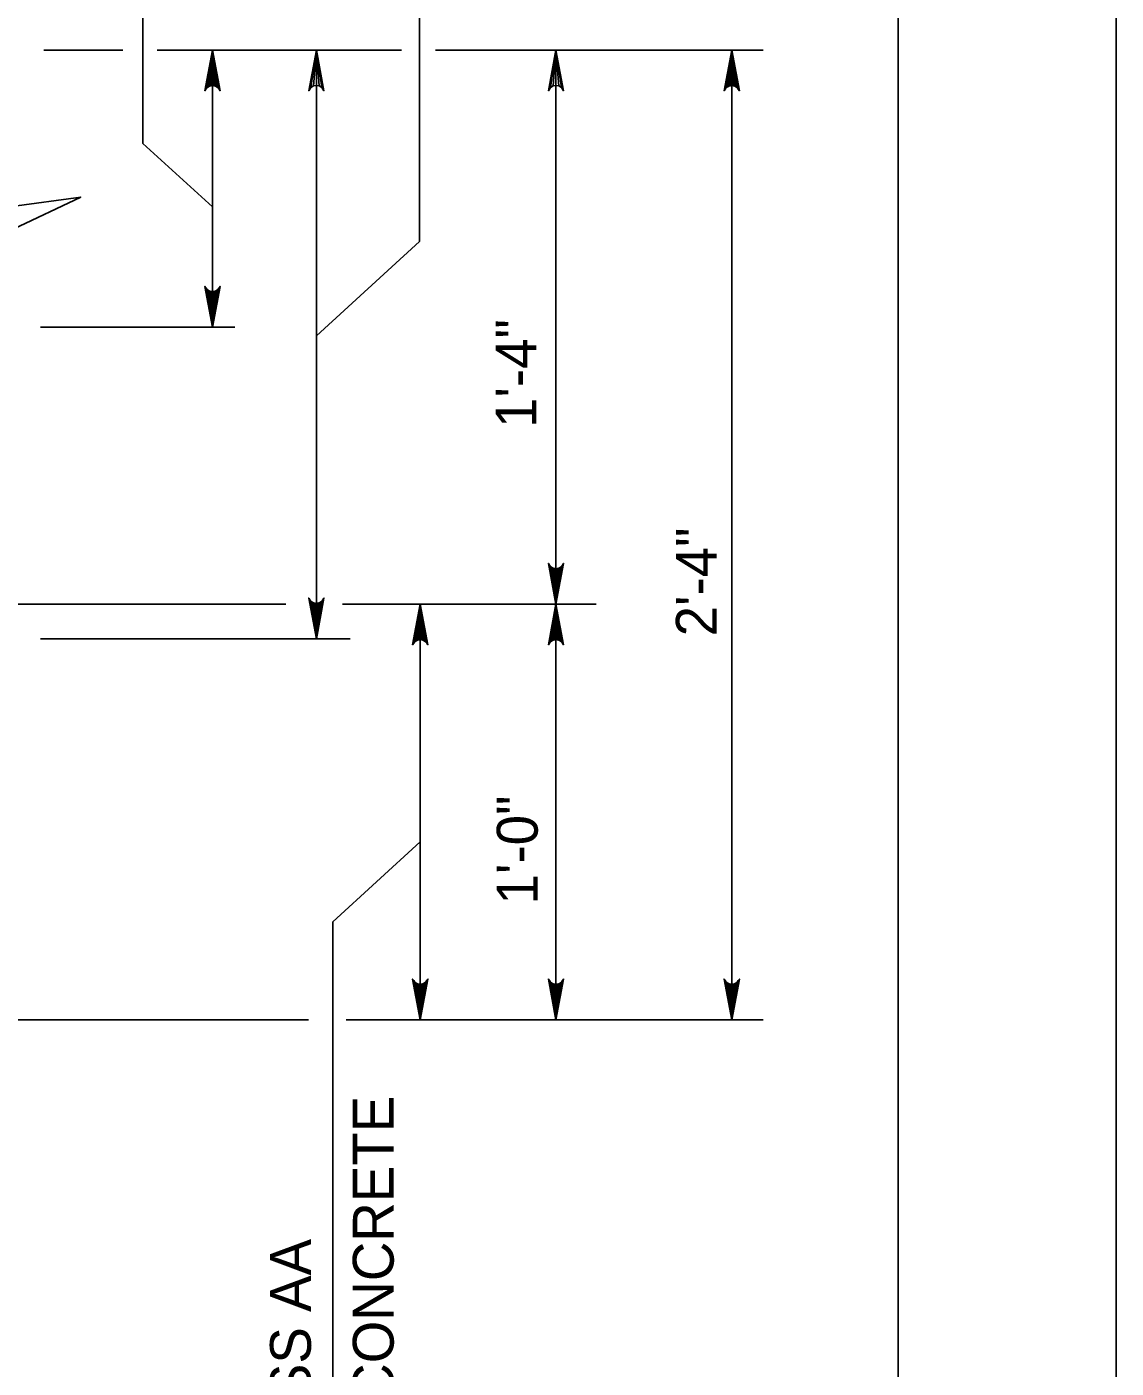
# Model space of a CAD drawing. Extents: x 638079 to 640019, y 297691 to 298879.
# Drawn here: x 639876.1 to 639956, y 298704.9 to 298803.3 of the extents above; entities that cross this region are included whole.
import ezdxf

# ---------------------------------------------------------------- set-up
doc = ezdxf.new("R2010")
doc.units = 0
doc.layers.add('1', color=7, linetype='Continuous')
doc.layers.add('PLT-BNDY', color=7, linetype='Continuous')

msp = doc.modelspace()

# ---------------------------------------------------------------- linework, layer by layer
at = {"layer": '1'}
for p, q in [((639884.632, 298794.725), (639884.632, 298832.259)), ((639904.923, 298787.525), (639904.923, 298830.816)), ((639877.35, 298801.575), (639883.152, 298801.575)), ((639885.681, 298801.575), (639903.606, 298801.575)), ((639889.73, 298781.254), (639889.73, 298801.575)), ((639897.35, 298758.394), (639897.35, 298801.575)), ((639906.081, 298801.575), (639930.125, 298801.575)), ((639914.931, 298760.936), (639914.931, 298801.575)), ((639927.83, 298730.456), (639927.83, 298801.575)), ((639884.632, 298794.725), (639889.73, 298790.073)), ((639904.923, 298787.525), (639897.35, 298780.616)), ((639877.116, 298781.254), (639891.37, 298781.254)), ((639803.122, 298760.936), (639895.12, 298760.936)), ((639899.281, 298760.936), (639917.88, 298760.936)), ((639904.97, 298730.456), (639904.97, 298760.936)), ((639914.931, 298730.456), (639914.931, 298760.936)), ((639877.116, 298758.394), (639899.824, 298758.394)), ((639898.549, 298737.641), (639904.97, 298743.5)), ((639898.549, 298685.764), (639898.549, 298737.641)), ((639803.122, 298730.456), (639896.763, 298730.456)), ((639899.538, 298730.456), (639930.125, 298730.456))]:
    msp.add_line(p, q, dxfattribs=at)
for points in [[(639940.033, 298300.226), (639940.033, 298864.226), (639154.033, 298864.226), (639154.033, 298300.226), (639940.033, 298300.226), (639940.033, 298326.585), (639740.033, 298326.585), (639740.033, 298391.263), (639940.033, 298391.263), (639940.033, 298420.226), (639740.033, 298420.226), (639740.033, 298300.226), (639818.835, 298300.226), (639818.835, 298326.585), (639818.835, 298300.226), (639895.835, 298300.226), (639895.835, 298326.585), (639895.835, 298314.269), (639940.033, 298314.269)], [(639889.73, 298801.575), (639890.29, 298798.592), (639890.21, 298798.707), (639890.13, 298798.822), (639890.03, 298798.881), (639889.93, 298798.941), (639889.83, 298798.958), (639889.73, 298798.975), (639889.63, 298798.958), (639889.53, 298798.941), (639889.43, 298798.881), (639889.33, 298798.822), (639889.251, 298798.707), (639889.171, 298798.592), (639889.73, 298801.575), (639889.251, 298798.707), (639889.33, 298798.822), (639889.73, 298801.575), (639889.43, 298798.881), (639889.53, 298798.941), (639889.73, 298801.575), (639889.63, 298798.958), (639889.73, 298798.975), (639889.73, 298801.575), (639889.83, 298798.958), (639889.93, 298798.941), (639889.73, 298801.575), (639890.03, 298798.881), (639890.13, 298798.822), (639889.73, 298801.575), (639890.21, 298798.707)], [(639897.35, 298801.575), (639897.91, 298798.592), (639897.75, 298798.822), (639897.55, 298798.941), (639897.35, 298798.975), (639897.15, 298798.941), (639896.95, 298798.822), (639896.791, 298798.592), (639897.35, 298801.575), (639896.95, 298798.822), (639897.15, 298798.941), (639897.35, 298801.575), (639897.35, 298798.975), (639897.55, 298798.941), (639897.35, 298801.575), (639897.75, 298798.822)], [(639914.931, 298801.575), (639915.49, 298798.592), (639915.331, 298798.822), (639915.131, 298798.941), (639914.931, 298798.975), (639914.731, 298798.941), (639914.531, 298798.822), (639914.371, 298798.592), (639914.931, 298801.575), (639914.531, 298798.822), (639914.731, 298798.941), (639914.931, 298801.575), (639914.931, 298798.975), (639915.131, 298798.941), (639914.931, 298801.575), (639915.331, 298798.822)], [(639927.83, 298801.575), (639928.39, 298798.592), (639928.31, 298798.707), (639928.23, 298798.822), (639928.13, 298798.881), (639928.03, 298798.941), (639927.93, 298798.958), (639927.83, 298798.975), (639927.73, 298798.958), (639927.63, 298798.941), (639927.53, 298798.881), (639927.43, 298798.822), (639927.351, 298798.707), (639927.271, 298798.592), (639927.83, 298801.575), (639927.351, 298798.707), (639927.43, 298798.822), (639927.83, 298801.575), (639927.53, 298798.881), (639927.63, 298798.941), (639927.83, 298801.575), (639927.73, 298798.958), (639927.83, 298798.975), (639927.83, 298801.575), (639927.93, 298798.958), (639928.03, 298798.941), (639927.83, 298801.575), (639928.13, 298798.881), (639928.23, 298798.822), (639927.83, 298801.575), (639928.31, 298798.707)], [(639875.099, 298791.946), (639869.914, 298789.409), (639880.063, 298790.789), (639875.099, 298788.428)], [(639889.73, 298781.254), (639889.171, 298784.237), (639889.251, 298784.122), (639889.33, 298784.007), (639889.43, 298783.948), (639889.53, 298783.888), (639889.63, 298783.871), (639889.73, 298783.854), (639889.83, 298783.871), (639889.93, 298783.888), (639890.03, 298783.948), (639890.13, 298784.007), (639890.21, 298784.122), (639890.29, 298784.237), (639889.73, 298781.254), (639890.21, 298784.122), (639890.13, 298784.007), (639889.73, 298781.254), (639890.03, 298783.948), (639889.93, 298783.888), (639889.73, 298781.254), (639889.83, 298783.871), (639889.73, 298783.854), (639889.73, 298781.254), (639889.63, 298783.871), (639889.53, 298783.888), (639889.73, 298781.254), (639889.43, 298783.948), (639889.33, 298784.007), (639889.73, 298781.254), (639889.251, 298784.122)], [(639914.931, 298760.936), (639914.371, 298763.919), (639914.451, 298763.804), (639914.531, 298763.689), (639914.631, 298763.63), (639914.731, 298763.57), (639914.831, 298763.553), (639914.931, 298763.536), (639915.031, 298763.553), (639915.131, 298763.57), (639915.231, 298763.63), (639915.331, 298763.689), (639915.41, 298763.804), (639915.49, 298763.919), (639914.931, 298760.936), (639915.41, 298763.804), (639915.331, 298763.689), (639914.931, 298760.936), (639915.231, 298763.63), (639915.131, 298763.57), (639914.931, 298760.936), (639915.031, 298763.553), (639914.931, 298763.536), (639914.931, 298760.936), (639914.831, 298763.553), (639914.731, 298763.57), (639914.931, 298760.936), (639914.631, 298763.63), (639914.531, 298763.689), (639914.931, 298760.936), (639914.451, 298763.804)], [(639897.35, 298758.394), (639896.791, 298761.377), (639896.871, 298761.262), (639896.95, 298761.147), (639897.05, 298761.088), (639897.15, 298761.028), (639897.25, 298761.011), (639897.35, 298760.994), (639897.45, 298761.011), (639897.55, 298761.028), (639897.65, 298761.088), (639897.75, 298761.147), (639897.83, 298761.262), (639897.91, 298761.377), (639897.35, 298758.394), (639897.83, 298761.262), (639897.75, 298761.147), (639897.35, 298758.394), (639897.65, 298761.088), (639897.55, 298761.028), (639897.35, 298758.394), (639897.45, 298761.011), (639897.35, 298760.994), (639897.35, 298758.394), (639897.25, 298761.011), (639897.15, 298761.028), (639897.35, 298758.394), (639897.05, 298761.088), (639896.95, 298761.147), (639897.35, 298758.394), (639896.871, 298761.262)], [(639904.97, 298760.936), (639905.53, 298757.953), (639905.45, 298758.068), (639905.37, 298758.183), (639905.27, 298758.242), (639905.17, 298758.302), (639905.07, 298758.319), (639904.97, 298758.336), (639904.87, 298758.319), (639904.77, 298758.302), (639904.67, 298758.242), (639904.57, 298758.183), (639904.491, 298758.068), (639904.411, 298757.953), (639904.97, 298760.936), (639904.491, 298758.068), (639904.57, 298758.183), (639904.97, 298760.936), (639904.67, 298758.242), (639904.77, 298758.302), (639904.97, 298760.936), (639904.87, 298758.319), (639904.97, 298758.336), (639904.97, 298760.936), (639905.07, 298758.319), (639905.17, 298758.302), (639904.97, 298760.936), (639905.27, 298758.242), (639905.37, 298758.183), (639904.97, 298760.936), (639905.45, 298758.068)], [(639914.931, 298760.936), (639915.49, 298757.953), (639915.41, 298758.068), (639915.331, 298758.183), (639915.231, 298758.242), (639915.131, 298758.302), (639915.031, 298758.319), (639914.931, 298758.336), (639914.831, 298758.319), (639914.731, 298758.302), (639914.631, 298758.242), (639914.531, 298758.183), (639914.451, 298758.068), (639914.371, 298757.953), (639914.931, 298760.936), (639914.451, 298758.068), (639914.531, 298758.183), (639914.931, 298760.936), (639914.631, 298758.242), (639914.731, 298758.302), (639914.931, 298760.936), (639914.831, 298758.319), (639914.931, 298758.336), (639914.931, 298760.936), (639915.031, 298758.319), (639915.131, 298758.302), (639914.931, 298760.936), (639915.231, 298758.242), (639915.331, 298758.183), (639914.931, 298760.936), (639915.41, 298758.068)], [(639904.97, 298730.456), (639904.411, 298733.439), (639904.491, 298733.324), (639904.57, 298733.209), (639904.67, 298733.15), (639904.77, 298733.09), (639904.87, 298733.073), (639904.97, 298733.056), (639905.07, 298733.073), (639905.17, 298733.09), (639905.27, 298733.15), (639905.37, 298733.209), (639905.45, 298733.324), (639905.53, 298733.439), (639904.97, 298730.456), (639905.45, 298733.324), (639905.37, 298733.209), (639904.97, 298730.456), (639905.27, 298733.15), (639905.17, 298733.09), (639904.97, 298730.456), (639905.07, 298733.073), (639904.97, 298733.056), (639904.97, 298730.456), (639904.87, 298733.073), (639904.77, 298733.09), (639904.97, 298730.456), (639904.67, 298733.15), (639904.57, 298733.209), (639904.97, 298730.456), (639904.491, 298733.324)], [(639914.931, 298730.456), (639914.371, 298733.439), (639914.451, 298733.324), (639914.531, 298733.209), (639914.631, 298733.15), (639914.731, 298733.09), (639914.831, 298733.073), (639914.931, 298733.056), (639915.031, 298733.073), (639915.131, 298733.09), (639915.231, 298733.15), (639915.331, 298733.209), (639915.41, 298733.324), (639915.49, 298733.439), (639914.931, 298730.456), (639915.41, 298733.324), (639915.331, 298733.209), (639914.931, 298730.456), (639915.231, 298733.15), (639915.131, 298733.09), (639914.931, 298730.456), (639915.031, 298733.073), (639914.931, 298733.056), (639914.931, 298730.456), (639914.831, 298733.073), (639914.731, 298733.09), (639914.931, 298730.456), (639914.631, 298733.15), (639914.531, 298733.209), (639914.931, 298730.456), (639914.451, 298733.324)], [(639927.83, 298730.456), (639927.271, 298733.439), (639927.351, 298733.324), (639927.43, 298733.209), (639927.53, 298733.15), (639927.63, 298733.09), (639927.73, 298733.073), (639927.83, 298733.056), (639927.93, 298733.073), (639928.03, 298733.09), (639928.13, 298733.15), (639928.23, 298733.209), (639928.31, 298733.324), (639928.39, 298733.439), (639927.83, 298730.456), (639928.31, 298733.324), (639928.23, 298733.209), (639927.83, 298730.456), (639928.13, 298733.15), (639928.03, 298733.09), (639927.83, 298730.456), (639927.93, 298733.073), (639927.83, 298733.056), (639927.83, 298730.456), (639927.73, 298733.073), (639927.63, 298733.09), (639927.83, 298730.456), (639927.53, 298733.15), (639927.43, 298733.209), (639927.83, 298730.456), (639927.351, 298733.324)]]:
    msp.add_lwpolyline(points, dxfattribs=at)
at = {"layer": 'PLT-BNDY'}
msp.add_lwpolyline([(639115.033, 298879.226), (639956.033, 298879.226), (639956.033, 298285.226), (639115.033, 298285.226)], close=True, dxfattribs=at)

# ---------------------------------------------------------------- texts
at = {"layer": '1'}
for s, p in [('1\'-4"', (639913.498, 298773.855)), ('2\'-4"', (639926.732, 298758.57)), ('1\'-0"', (639913.589, 298738.914)), ('CEMENT CONCRETE', (639903.025, 298684.317)), ('CLASS AA', (639896.953, 298694.758))]:
    msp.add_text(s, height=3, rotation=90, dxfattribs=at).set_placement(p)

doc.saveas('drawing.dxf')
